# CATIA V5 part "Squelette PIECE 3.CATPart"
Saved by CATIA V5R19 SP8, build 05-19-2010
Part number: Squelette PIECE 3
Publications: "Plan.2", "Esquisse.1", "Droite.1"
Bounding box of the stored display mesh (mm): x -6 to 0, y -9.5 to 12.5, z 0 to 12.5
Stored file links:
  C:\Users\ThinkMotion\Desktop\EU_thinkMotion\iao\IAO_MMS_Groupe3\jbuffard\jbuffard\Squelette PIECE 3.CATPart
  C:\Users\ThinkMotion\Desktop\EU_thinkMotion\iao\IAO_MMS_Groupe3\jbuffard\jbuffard\Mecanisme a coulisse a quatre elements de la griffe d'une camera.CATProduct
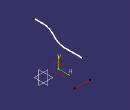
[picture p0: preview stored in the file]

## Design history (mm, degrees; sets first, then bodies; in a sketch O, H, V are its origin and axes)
Set1
  Point1: linked copy from another document
  Point2: linked copy from another document
  Plane1: linked copy from another document
  Point3 to Point5: linked copy from another document
Set2 "Set géométrique.6"
  Line1: type PtPt, FirstPoint Point1, SecondPoint Point2
  Sketch1 on Plane1, origin (-6, 0, 0), H (0, 1, 0), V (0, 0, 1)
    line L1 (-9.5, 12.5) -> (-5.6664, 12.5)
    point P1 (-9.5, 12.5)
    line L2 (2.0616, 8.5) -> (9.5, 8.5)
    point P2 (9.5, 8.5)
    reference projected point E1 (-9.5, 12.5) from Point3
    reference projected point E2 (9.5, 8.5) from Point4
    line L3 (-2.4844, 11.182) -> (-1.1204, 9.818)
    arc A1 centre (2.0616, 13) radius 4.5 from (-1.1204, 9.818) to (2.0616, 8.5) ccw
    arc A2 centre (-5.6664, 8) radius 4.5 from (-2.4844, 11.182) to (-5.6664, 12.5) ccw
    reference projected point E3 (0, 9) from Point5
    curve C1
    angle L3 L2 = 45
    radius A1 = 4.5
    radius A2 = 4.5
    parallelism: L2 L1
    coincidence: P1 E1, P2 E2, E3 A1
    horizontal: L1 H
    tangency: A1 L3, A1 L2, A2 L3, A2 L1
  Plane2: type Offset, RefPlane Plane1, Offset 0
Body1 (main body)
